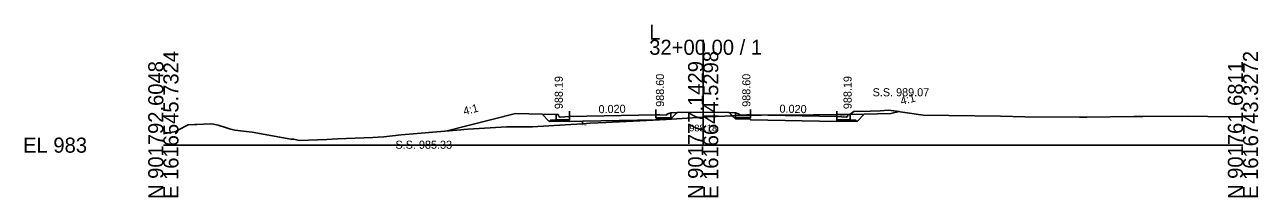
# Model space of a CAD drawing. Extents: x 1009 to 7438, y -1586 to 7964.
# Drawn here: x 3009.2 to 3237.7, y -86 to -53.9 of the extents above; entities that cross this region are included whole.
import ezdxf

# ---------------------------------------------------------------- set-up
doc = ezdxf.new("R2010")
doc.units = 0
for name, color, linetype in [('Exist Cross Section Cell', 7, 'Continuous'), ('Exist XS Center Line Elevation Label', 7, 'Continuous'), ('Exist XS Ground Line', 7, 'Continuous'), ('Prop XS Dump Level', 7, 'Continuous'), ('Prop XS Earthwork Shape', 7, 'Continuous'), ('Prop XS EOT Tick Mark', 7, 'Continuous'), ('Prop XS Finish Grade', 7, 'Continuous'), ('Prop XS Finish Grade CurbGutter', 7, 'Continuous'), ('Prop XS Finish Grade Earthwork', 7, 'Continuous'), ('Prop XS Finish Grade Pavement', 7, 'Continuous'), ('Prop XS Hydro Elevations', 7, 'Continuous'), ('Prop XS Pvmt Edge Slope', 7, 'Continuous'), ('Prop XS SE Text', 7, 'Continuous'), ('Prop XS Side Slope Text', 7, 'Continuous'), ('Prop XS SS Elevation Text', 7, 'Continuous'), ('Prop XS Subgrade CurbGutter', 7, 'Continuous'), ('Prop XS Subgrade Earthwork', 7, 'Continuous')]:
    doc.layers.add(name, color=color, linetype=linetype)

msp = doc.modelspace()

# ---------------------------------------------------------------- linework, layer by layer
at = {"layer": 'Exist Cross Section Cell'}
for p, q in [((3134.89, -76.27), (3134.89, -56.7)), ((3034.89, -76.27), (3134.89, -76.27)), ((3134.89, -76.27), (3234.89, -76.27))]:
    msp.add_line(p, q, dxfattribs=at)
at = {"layer": 'Exist XS Ground Line'}
for p, q in [((3138.88, -70.88), (3140.41, -70.8)), ((3140.41, -70.8), (3142.2, -70.77)), ((3142.2, -70.77), (3145.72, -70.73)), ((3145.72, -70.73), (3155.31, -70.63)), ((3155.31, -70.63), (3160.33, -70.56)), ((3160.33, -70.56), (3160.9, -70.56)), ((3160.9, -70.56), (3162.04, -70.55)), ((3162.04, -70.55), (3162.77, -70.04)), ((3162.77, -70.04), (3165.91, -69.96)), ((3165.91, -69.96), (3167.69, -69.92)), ((3167.69, -69.92), (3169.25, -69.75)), ((3169.25, -69.75), (3169.69, -69.81)), ((3169.69, -69.81), (3175.67, -70.69)), ((3175.67, -70.69), (3189.98, -70.91)), ((3037.57, -73.51), (3039.47, -72.5)), ((3039.47, -72.5), (3040.69, -72.45)), ((3040.69, -72.45), (3041.08, -72.43)), ((3041.08, -72.43), (3042.33, -72.4)), ((3042.33, -72.4), (3043.85, -72.3)), ((3043.85, -72.3), (3045.04, -72.55)), ((3045.04, -72.55), (3046.56, -73.03)), ((3046.56, -73.03), (3047.14, -73.23)), ((3093.4, -73.18), (3098.45, -72.87)), ((3098.45, -72.87), (3099.8, -72.87)), ((3099.8, -72.87), (3103.26, -72.87)), ((3103.26, -72.87), (3109.31, -72.52)), ((3109.31, -72.52), (3112.53, -72.3)), ((3112.53, -72.3), (3113.94, -72.2)), ((3113.94, -72.2), (3116.86, -72.07)), ((3116.86, -72.07), (3124.4, -71.72)), ((3124.4, -71.72), (3128.02, -71.5)), ((3128.02, -71.5), (3134.89, -71.09)), ((3134.89, -71.09), (3135.75, -71.04)), ((3135.75, -71.04), (3138.88, -70.88)), ((3189.98, -70.91), (3194.49, -71)), ((3194.49, -71), (3204.62, -71.06)), ((3204.62, -71.06), (3205.97, -71.05)), ((3205.97, -71.05), (3214.74, -70.98)), ((3214.74, -70.98), (3216.36, -70.98)), ((3216.36, -70.98), (3224.86, -70.9)), ((3224.86, -70.9), (3228.36, -70.93)), ((3228.36, -70.93), (3234.89, -71.02)), ((3034.89, -74.16), (3037.18, -73.73)), ((3037.18, -73.73), (3037.57, -73.51)), ((3047.14, -73.23), (3048.12, -73.5)), ((3048.12, -73.5), (3051.37, -73.84)), ((3051.37, -73.84), (3058.5, -75.13)), ((3058.5, -75.13), (3059.04, -75.15)), ((3059.04, -75.15), (3060.03, -75.39)), ((3060.03, -75.39), (3065.17, -75.25)), ((3065.17, -75.25), (3067.14, -75.07)), ((3067.14, -75.07), (3073.72, -74.84)), ((3073.72, -74.84), (3074.7, -74.77)), ((3074.7, -74.77), (3075.71, -74.72)), ((3075.71, -74.72), (3078.94, -74.37)), ((3078.94, -74.37), (3088.54, -73.53)), ((3088.54, -73.53), (3089.98, -73.41)), ((3089.98, -73.41), (3090.57, -73.35)), ((3090.57, -73.35), (3091.31, -73.31)), ((3091.31, -73.31), (3093.4, -73.18))]:
    msp.add_line(p, q, dxfattribs=at)
at = {"layer": 'Prop XS Dump Level'}
for p, q in [((3110.14, -70.96), (3126.14, -70.64)), ((3110.14, -70.96), (3126.14, -70.64)), ((3143.64, -70.64), (3159.64, -70.96)), ((3143.64, -70.64), (3159.64, -70.96))]:
    msp.add_line(p, q, dxfattribs=at)
at = {"layer": 'Prop XS Earthwork Shape'}
for points in [[(3099.8, -72.87), (3103.26, -72.87), (3109.31, -72.52), (3112.53, -72.3), (3112.53, -71.82), (3110.14, -71.87), (3110.14, -71.79), (3106.39, -71.86), (3105.05, -70.52), (3100.14, -70.42), (3087.23, -73.65), (3088.54, -73.53), (3089.98, -73.41), (3090.57, -73.35), (3091.31, -73.31), (3093.4, -73.18), (3098.45, -72.87)], [(3134.89, -71.09), (3135.75, -71.04), (3138.88, -70.88), (3140.29, -70.8), (3139.72, -70.23), (3139.67, -70.23), (3134.89, -70.13), (3130.12, -70.23), (3130.07, -70.23), (3128.89, -71.41), (3126.14, -71.47), (3126.14, -71.55), (3112.53, -71.82), (3112.53, -72.3), (3113.94, -72.2), (3116.86, -72.07), (3124.4, -71.72), (3128.02, -71.5)], [(3140.41, -70.8), (3140.89, -70.79), (3140.89, -71.16), (3141.14, -71.17), (3140.9, -71.41), (3140.29, -70.8)], [(3143.64, -70.75), (3143.64, -71.22), (3142.14, -71.19), (3141.14, -71.17), (3140.89, -71.16), (3140.89, -70.79), (3142.2, -70.77)], [(3159.64, -71.87), (3143.64, -71.55), (3143.64, -71.47), (3140.9, -71.41), (3141.14, -71.17), (3142.14, -71.19), (3143.64, -71.22), (3143.64, -70.75), (3145.72, -70.73), (3155.31, -70.63), (3159.64, -70.57), (3159.64, -70.96), (3159.64, -71.54), (3159.64, -71.79)], [(3165.91, -69.96), (3167.69, -69.92), (3169.25, -69.75), (3169.69, -69.81), (3171.19, -70.03), (3169.64, -70.42), (3164.73, -70.52), (3162.14, -70.58), (3161.89, -70.58), (3161.77, -70.6), (3161.68, -70.7), (3161.61, -70.95), (3161.52, -71.04), (3161.39, -71.06), (3159.64, -70.96), (3159.64, -70.57), (3160.33, -70.56), (3160.9, -70.56), (3162.04, -70.55), (3162.77, -70.04)], [(3162.14, -70.58), (3161.89, -70.58), (3161.77, -70.6), (3161.68, -70.7), (3161.61, -70.95), (3161.52, -71.04), (3161.39, -71.06), (3159.64, -70.96), (3159.64, -71.54), (3162.14, -71.59)], [(3163.14, -71.61), (3163.39, -71.86), (3164.73, -70.52), (3162.14, -70.58), (3162.14, -71.59)], [(3163.14, -71.61), (3163.39, -71.86), (3159.64, -71.79), (3159.64, -71.54), (3162.14, -71.59)]]:
    msp.add_lwpolyline(points, close=True, dxfattribs=at)
at = {"layer": 'Prop XS EOT Tick Mark'}
for p, q in [((3110.14, -70.96), (3110.14, -69.96)), ((3126.14, -70.64), (3126.14, -69.64)), ((3143.64, -70.64), (3143.64, -69.64)), ((3159.64, -70.96), (3159.64, -69.96))]:
    msp.add_line(p, q, dxfattribs=at)
at = {"layer": 'Prop XS Finish Grade'}
for p, q in [((3107.64, -70.58), (3105.05, -70.52)), ((3128.89, -70.26), (3130.12, -70.23)), ((3140.89, -70.26), (3139.67, -70.23)), ((3162.14, -70.58), (3164.73, -70.52))]:
    msp.add_line(p, q, dxfattribs=at)
at = {"layer": 'Prop XS Finish Grade CurbGutter'}
for p, q in [((3107.64, -70.58), (3107.89, -70.58)), ((3107.89, -70.58), (3108.02, -70.6)), ((3108.11, -70.7), (3108.02, -70.6)), ((3108.18, -70.95), (3108.11, -70.7)), ((3126.14, -70.64), (3126.89, -70.65)), ((3126.14, -70.64), (3128.14, -70.68)), ((3128.14, -70.51), (3128.89, -70.26)), ((3128.14, -70.68), (3128.14, -70.51)), ((3141.64, -70.51), (3140.89, -70.26)), ((3141.64, -70.68), (3141.64, -70.51)), ((3143.64, -70.64), (3141.64, -70.68)), ((3143.64, -70.64), (3142.89, -70.65)), ((3161.61, -70.95), (3161.68, -70.7)), ((3161.68, -70.7), (3161.77, -70.6)), ((3161.89, -70.58), (3161.77, -70.6)), ((3162.14, -70.58), (3161.89, -70.58)), ((3108.27, -71.04), (3108.18, -70.95)), ((3108.39, -71.06), (3108.27, -71.04)), ((3110.14, -70.96), (3108.39, -71.06)), ((3159.64, -70.96), (3161.39, -71.06)), ((3161.39, -71.06), (3161.52, -71.04)), ((3161.52, -71.04), (3161.61, -70.95))]:
    msp.add_line(p, q, dxfattribs=at)
at = {"layer": 'Prop XS Finish Grade Earthwork'}
for p, q in [((3100.14, -70.42), (3087.23, -73.65)), ((3105.05, -70.52), (3100.14, -70.42)), ((3130.12, -70.23), (3134.89, -70.13)), ((3134.89, -70.13), (3139.67, -70.23)), ((3164.73, -70.52), (3169.64, -70.42)), ((3169.64, -70.42), (3171.19, -70.03))]:
    msp.add_line(p, q, dxfattribs=at)
at = {"layer": 'Prop XS Finish Grade Pavement'}
for p, q in [((3110.14, -70.96), (3126.14, -70.64)), ((3143.64, -70.64), (3159.64, -70.96))]:
    msp.add_line(p, q, dxfattribs=at)
at = {"layer": 'Prop XS Pvmt Edge Slope'}
for p, q in [((3106.64, -71.61), (3106.39, -71.86)), ((3107.64, -71.59), (3106.64, -71.61)), ((3127.64, -71.19), (3128.89, -71.16)), ((3127.64, -71.19), (3128.64, -71.17)), ((3128.64, -71.17), (3128.89, -71.41)), ((3142.14, -71.19), (3140.89, -71.16)), ((3141.14, -71.17), (3140.9, -71.41)), ((3142.14, -71.19), (3141.14, -71.17)), ((3162.14, -71.59), (3163.14, -71.61)), ((3163.14, -71.61), (3163.39, -71.86))]:
    msp.add_line(p, q, dxfattribs=at)
at = {"layer": 'Prop XS Subgrade CurbGutter'}
for p, q in [((3107.64, -71.59), (3107.64, -70.58)), ((3126.14, -70.64), (3126.14, -71.22)), ((3128.89, -71.16), (3128.89, -70.26)), ((3140.89, -71.16), (3140.89, -70.26)), ((3143.64, -70.64), (3143.64, -71.22)), ((3162.14, -71.59), (3162.14, -70.58)), ((3110.14, -71.54), (3107.64, -71.59)), ((3110.14, -70.96), (3110.14, -71.54)), ((3126.14, -71.22), (3127.64, -71.19)), ((3143.64, -71.22), (3142.14, -71.19)), ((3159.64, -70.96), (3159.64, -71.54)), ((3159.64, -71.54), (3162.14, -71.59))]:
    msp.add_line(p, q, dxfattribs=at)
at = {"layer": 'Prop XS Subgrade Earthwork'}
for p, q in [((3106.39, -71.86), (3105.05, -70.52)), ((3128.89, -71.41), (3130.07, -70.23)), ((3140.9, -71.41), (3139.72, -70.23)), ((3159.64, -71.87), (3159.64, -70.57)), ((3159.64, -71.87), (3159.64, -70.57)), ((3163.39, -71.86), (3164.73, -70.52)), ((3110.14, -71.79), (3106.39, -71.86)), ((3110.14, -71.87), (3110.14, -71.79)), ((3112.53, -71.82), (3110.14, -71.87)), ((3112.53, -71.82), (3126.14, -71.55)), ((3112.53, -71.82), (3112.53, -72.3)), ((3112.53, -71.82), (3112.53, -72.3)), ((3126.14, -71.47), (3128.89, -71.41)), ((3126.14, -71.55), (3126.14, -71.47)), ((3143.64, -71.47), (3140.9, -71.41)), ((3143.64, -71.55), (3143.64, -71.47)), ((3159.64, -71.87), (3143.64, -71.55)), ((3159.64, -71.87), (3159.64, -71.79)), ((3159.64, -71.79), (3163.39, -71.86))]:
    msp.add_line(p, q, dxfattribs=at)

# ---------------------------------------------------------------- texts
at = {"layer": 'Exist Cross Section Cell'}
for s, p in [('L', (3124.89, -56.7)), ('32+00.00 / 1', (3124.89, -59.5)), ('EL 983', (3008.89, -77.67))]:
    msp.add_text(s, height=2.8, dxfattribs=at).set_placement(p)
for s, p in [('E 1616545.7324', (3037.69, -86.27)), ('E 1616644.5298', (3137.69, -86.27)), ('E 1616743.3272', (3237.69, -86.27)), ('N 901792.6048', (3034.89, -86.27)), ('N 901777.1429', (3134.89, -86.27)), ('N 901761.6811', (3234.89, -86.27))]:
    msp.add_text(s, height=2.8, rotation=90, dxfattribs=at).set_placement(p)
at = {"layer": 'Exist XS Center Line Elevation Label'}
msp.add_text('988.18', height=1.25, dxfattribs=at).set_placement((3132.34, -73.72))
at = {"layer": 'Prop XS Dump Level'}
for p in [(3160.33, -70.86), (3160.33, -70.86), (3112.53, -72.6), (3112.53, -72.6)]:
    msp.add_text('Eop', height=0.3, dxfattribs=at).set_placement(p)
at = {"layer": 'Prop XS Hydro Elevations'}
for s, p in [('988.19', (3108.89, -69.58)), ('988.60', (3127.64, -69.15)), ('988.60', (3143.64, -69.15)), ('988.19', (3162.39, -69.58))]:
    msp.add_text(s, height=1.5, rotation=90, dxfattribs=at).set_placement(p)
at = {"layer": 'Prop XS SE Text'}
for rotation, p in [(1.1458, (3115.52, -70.35)), (358.8542, (3149.02, -70.24))]:
    msp.add_text('0.020', height=1.5, rotation=rotation, dxfattribs=at).set_placement(p)
at = {"layer": 'Prop XS Side Slope Text'}
for p in [(3171.63, -68.83), (3090.65, -70.7)]:
    msp.add_text('4:1', height=1.5, rotation=14.0362, dxfattribs=at).set_placement(p)
at = {"layer": 'Prop XS SS Elevation Text'}
for s, p in [('S.S. 989.07', (3166.28, -67.2)), ('S.S. 985.33', (3077.89, -76.94))]:
    msp.add_text(s, height=1.5, dxfattribs=at).set_placement(p)

doc.saveas('drawing.dxf')
